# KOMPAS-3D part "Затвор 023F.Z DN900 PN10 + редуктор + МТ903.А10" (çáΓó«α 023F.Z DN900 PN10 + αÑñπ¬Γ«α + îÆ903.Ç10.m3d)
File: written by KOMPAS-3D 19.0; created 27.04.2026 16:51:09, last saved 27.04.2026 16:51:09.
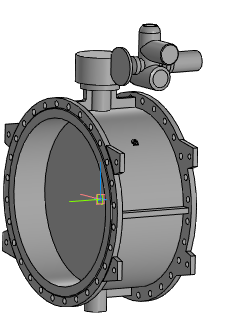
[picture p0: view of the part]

Document properties: Полное имя файла: ..\..\Затвор 023F.Z DN400-DN1600 + редуктор + МТ903\Затвор 023F.Z DN900 PN10 + редуктор + МТ903.А10.a3d

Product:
- Part/product: Затвор 023F.Z DN900 PN10 + редуктор + МТ903.А10
    Масса: 1027.22

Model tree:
1. Операция без истории:1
